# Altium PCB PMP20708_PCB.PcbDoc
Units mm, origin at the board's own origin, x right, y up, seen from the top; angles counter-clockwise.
Board outline 41 x 30 mm, 2 copper layers (Top Layer, Bottom Layer), stack 1.575 mm thick; 39 components, 23 nets, 89 pads, 0 vias.
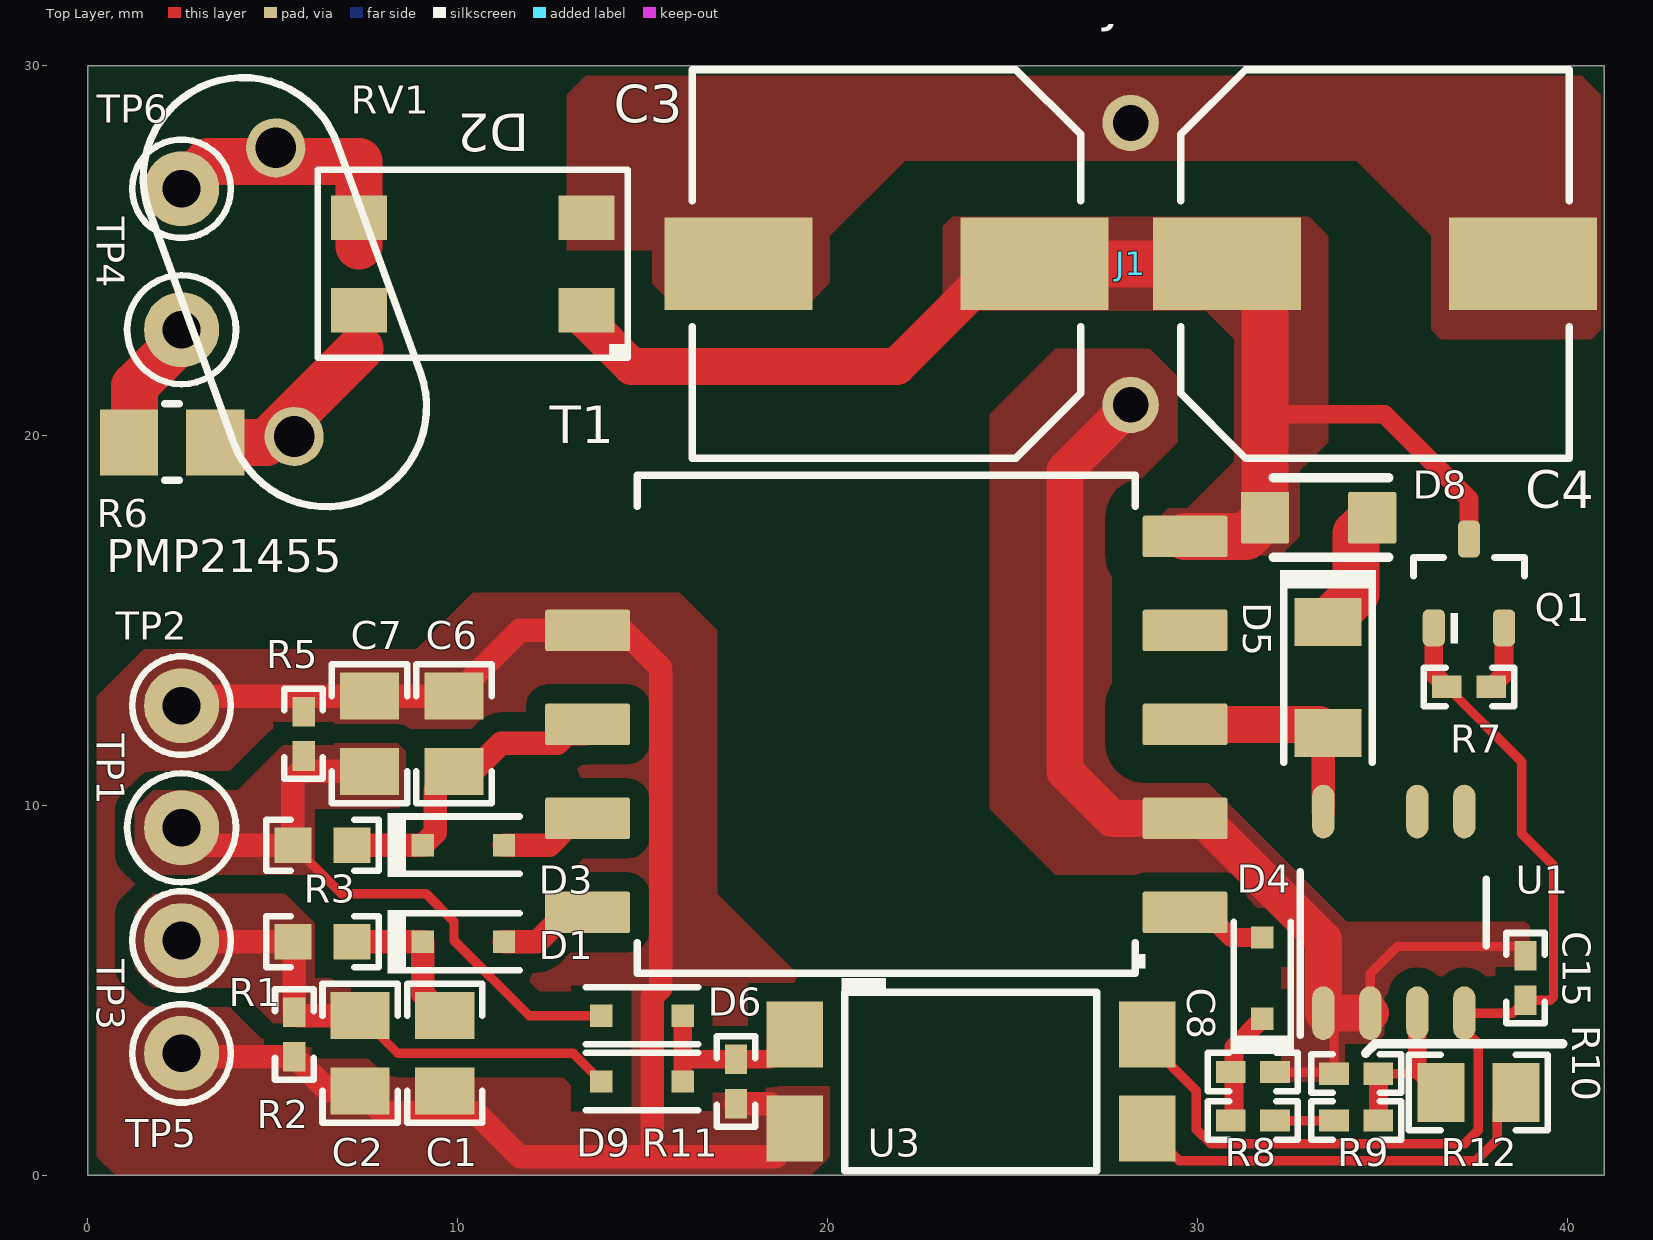
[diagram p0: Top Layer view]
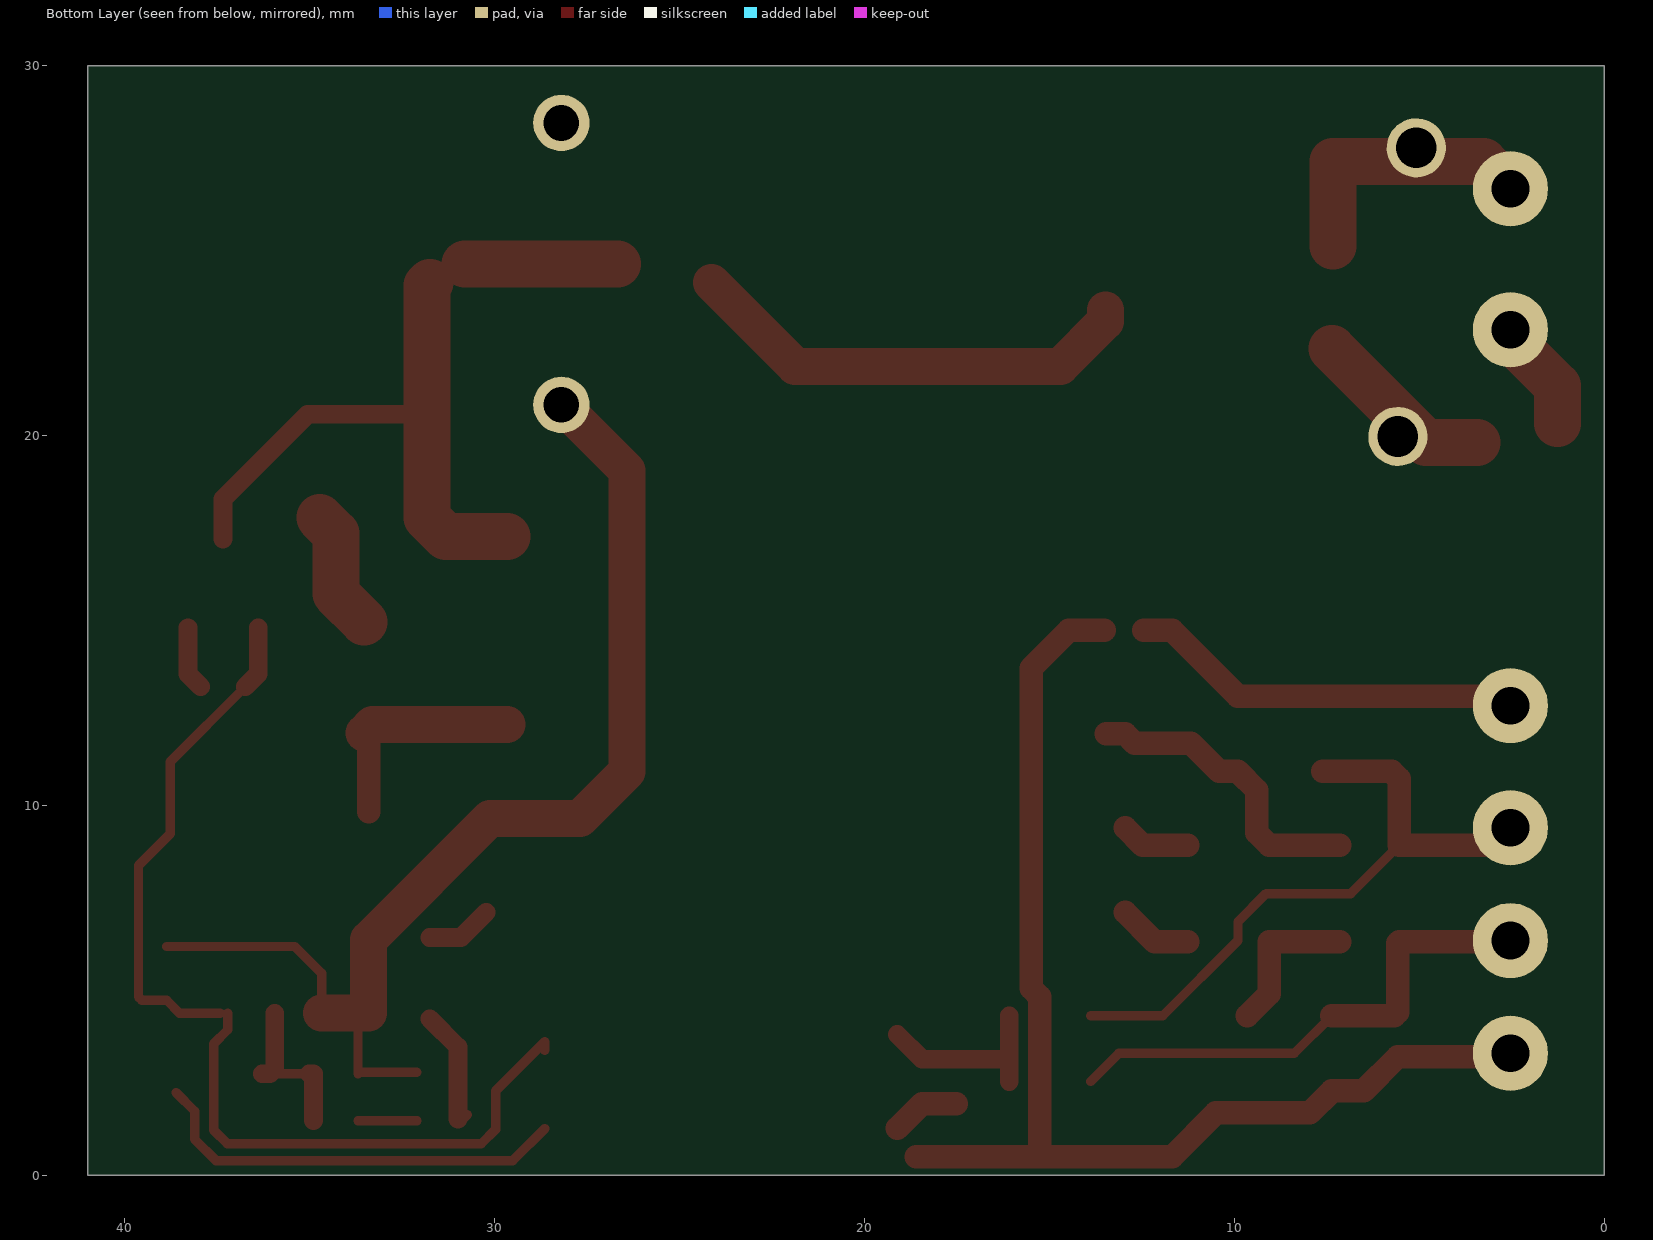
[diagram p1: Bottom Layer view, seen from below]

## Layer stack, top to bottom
Top Solder: solder mask 0.0102, Solder Resist, Dk 3.5
Top Layer: signal copper 0.0356
Dielectric1: core 1.5037, FR-4, Dk 4.8
Bottom Layer: signal copper 0.0356
Bottom Solder: solder mask 0.0102, Solder Resist, Dk 3.5

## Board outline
0,0 41,0 41,30 0,30

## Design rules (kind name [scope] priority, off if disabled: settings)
AcuteAngle [All] p1: minimum=4.50000000000000E+0001 checktracksonly=FALSE
AssemblyTestPointUsage [All] p1: valid=2
Clearance Clearance_2 [InNetClass('HV') vs Not InNetClass('HV')] p1: gap=1.016 ignorepadtopadclearanceinfootprint=FALSE except(0: Arc-Hole Track-Hole SMDPad-Hole THPad-Hole Via-Hole Fill-Hole Poly-Hole Region-Hole Text-Hole)
Clearance Clearance_Keepouts [((IsTrack Or IsArc) And Not InPoly) And IsFree and IsKeepOut vs ((IsTrack Or IsArc) And Not InPoly) And IsFree and IsKeepOut] p2: gap=0 ignorepadtopadclearanceinfootprint=FALSE
Clearance Clearance_BoardEdge_MountingHoles [OnCopper and InComponentClass('Mounting Holes') vs IsKeepOut] p3: gap=1.016 ignorepadtopadclearanceinfootprint=FALSE except(0: Arc-Hole Track-Hole SMDPad-Hole THPad-Hole Via-Hole Fill-Hole Poly-Hole Region-Hole Text-Hole)
Clearance Clearance_BoardEdge_Poly [OnCopper and InPoly vs IsKeepOut] p4: gap=0.635 ignorepadtopadclearanceinfootprint=FALSE except(0: Arc-Hole Track-Hole SMDPad-Hole THPad-Hole Via-Hole Fill-Hole Poly-Hole Region-Hole Text-Hole)
Clearance Clearance_BoardEdge [OnCopper and Not InComponentClass('Logo') and not InComponentClass('FiducialMark') and not InRegion(1000,500,4000,800) and Not IsKeepout vs IsKeepOut] p5: gap=1.905 ignorepadtopadclearanceinfootprint=FALSE except(0: Arc-Hole Track-Hole SMDPad-Hole THPad-Hole Via-Hole Fill-Hole Poly-Hole Region-Hole Text-Hole)
Clearance Clearance_Poly [InPolygon] p6: gap=0.508 ignorepadtopadclearanceinfootprint=FALSE except(0: Arc-Hole Track-Hole SMDPad-Hole THPad-Hole Via-Hole Fill-Hole Poly-Hole Region-Hole Text-Hole)
Clearance [All] p7: gap=0.2 ignorepadtopadclearanceinfootprint=FALSE except(0: Arc-Hole Track-Hole SMDPad-Hole THPad-Hole Via-Hole Fill-Hole Poly-Hole Region-Hole Text-Hole)
ComponentClearance ComponentClearance_MountingHoles_FiducialMarks [InComponentClass('Mounting Holes') vs InComponentClass('FiducialMark')] p1: gap=0.508 collisioncheckmode=3 verticalgap=0.254 showdistances=FALSE
ComponentClearance ComponentClearance_Shunt [InComponentClass('Header') vs InComponentClass('Shunt')] p2: gap=0 collisioncheckmode=3 verticalgap=0 showdistances=FALSE
ComponentClearance ComponentClearance_Logo [InComponentClass('Logo')] p3: gap=0.127 collisioncheckmode=3 verticalgap=0.254 showdistances=FALSE
ComponentClearance ComponentClearance_ScrewToNut [(HasFootprint('NY PMS 440 0025 PH')) vs (HasFootprint('Keystone_1902C'))] p4: gap=0.508 collisioncheckmode=3 verticalgap=2540 showdistances=FALSE
ComponentClearance ComponentClearance_MountingHoles [InComponentClass('Mounting Holes')] p5: gap=0.508 collisioncheckmode=3 verticalgap=0.254 showdistances=FALSE
ComponentClearance ComponentClearance_SmallPassives [HasFootprint('0201*') or HasFootprint('0402*') or HasFootprint('0508') or HasFootprint('0603*') or HasFootprint('0612') or HasFootprint('0805*') or HasFootprint('0815*') or HasFootprint('0830*') or HasFootprint('1206*') or HasFootprint('1210*') or HasFootprint('1808*') or HasFootprint('1812*') or HasFootprint('1825*') or HasFootprint('2010*') or HasFootprint('2220*') or HasFootprint('2225*') or HasFootprint('2512*') or HasFootprint('2728*') or HasFootprint('3518*') vs HasFootprint('0201*') or HasFootprint('0402*') or HasFootprint('0508') or HasFootprint('0603*') or HasFootprint('0612') or HasFootprint('0805*') or HasFootprint('0815*') or HasFootprint('0830*') or HasFootprint('1206*') or HasFootprint('1210*') or HasFootprint('1808*') or HasFootprint('1812*') or HasFootprint('1825*') or HasFootprint('2010*') or HasFootprint('2220*') or HasFootprint('2225*') or HasFootprint('2512*') or HasFootprint('2728*') or HasFootprint('3518*')] p6: gap=0.508 collisioncheckmode=3 verticalgap=0.508 showdistances=FALSE
ComponentClearance ComponentClearance_THtoSMT [IsThruComponent vs IsSMTComponent] p7: gap=0.254 collisioncheckmode=3 verticalgap=0.254 showdistances=FALSE
ComponentClearance ComponentClearance_THtoTH [IsThruComponent vs IsThruComponent] p8: gap=0.254 collisioncheckmode=3 verticalgap=0.254 showdistances=FALSE
ComponentClearance [All] p9: gap=0.254 collisioncheckmode=3 verticalgap=0.254 showdistances=FALSE
DiffPairsRouting [All] p1: maxlimit=2.54 minlimit=0.254 mostfreqgap=0.254 toplayer_minwidth=0.381 toplayer_maxwidth=0.381 toplayer_prefwidth=0.381 bottomlayer_minwidth=0.381 bottomlayer_maxwidth=0.381 bottomlayer_prefwidth=0.381 maxuncoupledlength=25.4
FabricationTestPointUsage TestPointUsage [All] p1: valid=2 allowmultiple=FALSE
FabricationTestpoint Testpoint [All] p1: side=3 testpointundercomponent=TRUE minsize=1.016 maxsize=2.54 preferedsize=1.524 minholesize=0 maxholesize=1.016 preferedholesize=0.813 testpointgrid=0.025 allowsidetop=TRUE allowsidebottom=TRUE usegrid=TRUE gridtolerance=0
FanoutControl Fanout_LCC [IsLCC] p1: bgadir=Out bgaviamode=Centered fanoutstyle=Auto fanoutdirection=Alternating viagrid=0.025 // Fanout_LCC (Default Rule)
FanoutControl Fanout_BGA [IsBGA] p2: bgadir=Out bgaviamode=Centered fanoutstyle=Auto fanoutdirection=Alternating viagrid=0.025 // Fanout_BGA (Default Rule)
FanoutControl Fanout_Default [All] p4: bgadir=Out bgaviamode=Centered fanoutstyle=Auto fanoutdirection=Alternating viagrid=0.025 // Fanout_Default (Default Rule)
FanoutControl Fanout_Small [(CompPinCount < 5)] p5: bgadir=Out bgaviamode=Centered fanoutstyle=Auto fanoutdirection=OutThenIn viagrid=0.025 // Fanout_Small (Default Rule)
Height [All] p1: minheight=0 maxheight=76.2 prefheight=12.7
HoleSize [All] p1: absolutevalues=TRUE maxlimit=6.375 minlimit=0.178 maxpercent=80.000 minpercent=20.000
MinimumAnnularRing MinimumAnnularRing_ThermalPadVias [IsVia and InAnyComponent] p1: minimumring=0.15
MinimumAnnularRing [All] p2: minimumring=0.124
MinimumSolderMaskSliver MinimumSolderMaskSliver_Logo [InComponentClass('Logo') vs InComponentClass('Logo')] p1: minsoldermaskwidth=0.018
MinimumSolderMaskSliver [All] p2: minsoldermaskwidth=0.051
PlaneConnect [All] p1: planeconnectstyle=Relief reliefexpansion=0.254 reliefentries=4 reliefconductorwidth=0.254 reliefairgap=0.254
PolygonConnect PolygonConnect_12 [All vs IsNamedPolygon('VREC') Or  IsNamedPolygon('24V') Or  IsNamedPolygon('C3_2') Or  IsNamedPolygon('GND') Or  IsNamedPolygon('RTN') Or  IsNamedPolygon('5V')] p1: connectstyle=Direct reliefconductorwidth=0.254 reliefentries=4 polygonreliefangle="90 Angle" airgapwidth=0.254
PolygonConnect PolygonConnect_11 [All vs IsNamedPolygon('VREC') Or  IsNamedPolygon('RTN') Or  IsNamedPolygon('C3_2')] p2: connectstyle=Direct reliefconductorwidth=0.254 reliefentries=4 polygonreliefangle="90 Angle" airgapwidth=0.254
PolygonConnect PolygonConnect_10 [All vs IsNamedPolygon('RTN') Or  IsNamedPolygon('C3_2') Or  IsNamedPolygon('VREC')] p3: connectstyle=Direct reliefconductorwidth=0.254 reliefentries=4 polygonreliefangle="90 Angle" airgapwidth=0.254
PolygonConnect PolygonConnect_9 [All vs IsNamedPolygon('C11_1') Or  IsNamedPolygon('Vin') Or  IsNamedPolygon('Vin') Or  IsNamedPolygon('5V') Or  IsNamedPolygon('D6_2') Or  IsNamedPolygon('Q3_3') Or  IsNamedPolygon('GND2') Or  IsNamedPolygon('GND2') Or  IsNamedPolygon('GND') Or  IsNamedPolygon('Q3_4') Or  IsNamedPolygon('12V5') Or  IsNamedPolygon('GND') Or  IsNamedPolygon('12V5') Or  IsNamedPolygon('D3_1')] p4: connectstyle=Direct reliefconductorwidth=0.254 reliefentries=4 polygonreliefangle="90 Angle" airgapwidth=0.254
PolygonConnect PolygonConnect_8 [All vs IsNamedPolygon('C11_1') Or  IsNamedPolygon('Vin') Or  IsNamedPolygon('12V5') Or  IsNamedPolygon('Q3_3') Or  IsNamedPolygon('GND2') Or  IsNamedPolygon('GND2') Or  IsNamedPolygon('5V') Or  IsNamedPolygon('Q3_4') Or  IsNamedPolygon('12V5')] p5: connectstyle=Direct reliefconductorwidth=0.254 reliefentries=4 polygonreliefangle="90 Angle" airgapwidth=0.254
PolygonConnect PolygonConnect_7 [All vs IsNamedPolygon('GND2') Or  IsNamedPolygon('GND2') Or  IsNamedPolygon('5V') Or  IsNamedPolygon('12V5') Or  IsNamedPolygon('12V5') Or  IsNamedPolygon('C11_1')] p6: connectstyle=Direct reliefconductorwidth=0.254 reliefentries=4 polygonreliefangle="90 Angle" airgapwidth=0.254
PolygonConnect PolygonConnect_6 [All vs IsNamedPolygon('GND2') Or  IsNamedPolygon('SGND') Or  IsNamedPolygon('GND1') Or  IsNamedPolygon('C901_1') Or  IsNamedPolygon('SGND') Or  IsNamedPolygon('GND2') Or  IsNamedPolygon('GND1')] p7: connectstyle=Direct reliefconductorwidth=0.254 reliefentries=4 polygonreliefangle="90 Angle" airgapwidth=0.254
PolygonConnect PolygonConnect_5 [All vs IsNamedPolygon('GND1') Or  IsNamedPolygon('GND1')] p8: connectstyle=Direct reliefconductorwidth=0.254 reliefentries=4 polygonreliefangle="90 Angle" airgapwidth=0.254
PolygonConnect PolygonConnect_4 [All vs IsNamedPolygon('C21_1') Or  IsNamedPolygon('C5_1') Or  IsNamedPolygon('C12_2') Or  IsNamedPolygon('C2_2') Or  IsNamedPolygon('C13_1') Or  IsNamedPolygon('C28_1') Or  IsNamedPolygon('C6_1') Or  IsNamedPolygon('GND') Or  IsNamedPolygon('GND2') Or  IsNamedPolygon('C14_1') Or  IsNamedPolygon('C13_1') Or  IsNamedPolygon('Q1_3') Or  IsNamedPolygon('C14_1') Or  IsNamedPolygon('C5_1') Or  IsNamedPolygon('GND2') Or  IsNamedPolygon('C28_1') Or  IsNamedPolygon('D5_2') Or  IsNamedPolygon('D6_2') Or  IsNamedPolygon('D2_1') Or  IsNamedPolygon('C12_2') Or  IsNamedPolygon('D2_1') Or  IsNamedPolygon('C4_1') Or  IsNamedPolygon('C4_1') Or  IsNamedPolygon('C2_2') Or  IsNamedPolygon('GND') Or  IsNamedPolygon('C33_1') Or  IsNamedPolygon('C9_1')] p9: connectstyle=Direct reliefconductorwidth=0.254 reliefentries=4 polygonreliefangle="90 Angle" airgapwidth=0.254
PolygonConnect PolygonConnect_3 [All vs IsNamedPolygon('C28_1') Or  IsNamedPolygon('C12_2') Or  IsNamedPolygon('C28_1') Or  IsNamedPolygon('C9_1') Or  IsNamedPolygon('D5_2') Or  IsNamedPolygon('C12_2') Or  IsNamedPolygon('C2_2') Or  IsNamedPolygon('C14_1') Or  IsNamedPolygon('C4_1') Or  IsNamedPolygon('C14_1') Or  IsNamedPolygon('D6_2') Or  IsNamedPolygon('GND2') Or  IsNamedPolygon('Q1_3') Or  IsNamedPolygon('C5_1') Or  IsNamedPolygon('D2_1') Or  IsNamedPolygon('C4_1') Or  IsNamedPolygon('C13_1') Or  IsNamedPolygon('C5_1') Or  IsNamedPolygon('C13_1') Or  IsNamedPolygon('C33_1') Or  IsNamedPolygon('D2_1') Or  IsNamedPolygon('GND') Or  IsNamedPolygon('GND') Or  IsNamedPolygon('GND2') Or  IsNamedPolygon('C2_2') Or  IsNamedPolygon('C6_1') Or  IsNamedPolygon('C21_1')] p10: connectstyle=Direct reliefconductorwidth=0.254 reliefentries=4 polygonreliefangle="90 Angle" airgapwidth=0.254
PolygonConnect PolygonConnect_2 [All vs IsNamedPolygon('C21_1') Or  IsNamedPolygon('C4_1') Or  IsNamedPolygon('D5_2') Or  IsNamedPolygon('C5_1') Or  IsNamedPolygon('C14_1') Or  IsNamedPolygon('C13_1') Or  IsNamedPolygon('C4_1') Or  IsNamedPolygon('C33_1') Or  IsNamedPolygon('C12_2') Or  IsNamedPolygon('D2_1') Or  IsNamedPolygon('C2_2') Or  IsNamedPolygon('C28_1') Or  IsNamedPolygon('C12_2') Or  IsNamedPolygon('D2_1') Or  IsNamedPolygon('C5_1') Or  IsNamedPolygon('Q1_3') Or  IsNamedPolygon('GND') Or  IsNamedPolygon('D6_2') Or  IsNamedPolygon('C6_1') Or  IsNamedPolygon('C2_2') Or  IsNamedPolygon('C14_1') Or  IsNamedPolygon('C28_1') Or  IsNamedPolygon('C13_1') Or  IsNamedPolygon('C9_1') Or  IsNamedPolygon('GND')] p11: connectstyle=Direct reliefconductorwidth=0.254 reliefentries=4 polygonreliefangle="90 Angle" airgapwidth=0.254
PolygonConnect PolygonConnect_1 [All vs IsNamedPolygon('C28_1') Or  IsNamedPolygon('D5_2') Or  IsNamedPolygon('C5_1') Or  IsNamedPolygon('C5_1') Or  IsNamedPolygon('D2_1') Or  IsNamedPolygon('C21_1') Or  IsNamedPolygon('C9_1') Or  IsNamedPolygon('C4_1') Or  IsNamedPolygon('C14_1') Or  IsNamedPolygon('C28_1') Or  IsNamedPolygon('C6_1') Or  IsNamedPolygon('C12_2') Or  IsNamedPolygon('C33_1') Or  IsNamedPolygon('C4_1') Or  IsNamedPolygon('C13_1') Or  IsNamedPolygon('C12_2') Or  IsNamedPolygon('D6_2') Or  IsNamedPolygon('C2_2') Or  IsNamedPolygon('C14_1') Or  IsNamedPolygon('D2_1') Or  IsNamedPolygon('C2_2') Or  IsNamedPolygon('C13_1')] p12: connectstyle=Direct reliefconductorwidth=0.254 reliefentries=4 polygonreliefangle="90 Angle" airgapwidth=0.254
PolygonConnect [All] p13: connectstyle=Relief reliefconductorwidth=0.254 reliefentries=4 polygonreliefangle="90 Angle" airgapwidth=0.254
RoutingVias ThermalPadVias [IsVia and InAnyComponent] p1: holewidth=0.2 width=0.5 viastyle="Through Hole" minholewidth=0.2 minwidth=0.5 maxholewidth=0.33 maxwidth=0.6
RoutingVias [All] p2: holewidth=0.406 width=0.864 viastyle="Through Hole" minholewidth=0.2 minwidth=0.508 maxholewidth=1.016 maxwidth=1.651
SilkToBoardRegionClearance [Not ((IsComment or IsDesignator) And (Hide <> 'False')) and not InRegion(1000,500,4000,800)] p1:
SilkToSilkClearance SilkToSilkClearance_Pb-FreeLogo [(HasFootprint('Pb-Free_Overlay_Medium') OR HasFootprint('Pb-Free_Overlay_Small')) vs (HasFootprint('Pb-Free_Overlay_Medium') OR HasFootprint('Pb-Free_Overlay_Small'))] p1: silktosilkclearance=0
SilkToSilkClearance [All] p2: silktosilkclearance=0.025
SilkToSolderMaskClearance "Silk to Solder Mask Opening" [All] p1: minsilkscreentomaskgap=0.025 clearancetoexposedcopper=FALSE
SolderMaskExpansion [All] p1: expansion=0.05
Width [All] p1: maxlimit=2.54 minlimit=0.152 preferedwidth=0.254 checkconnectedcopper=TRUE
14 further rules are at their usual default settings.

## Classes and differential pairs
net class HV: NetD2_3 NetD2_4 NetD5_1 NetD5_2 NetR6_1 VREC

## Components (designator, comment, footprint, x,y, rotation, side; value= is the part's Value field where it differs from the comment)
C1 "C2012X5R1V106K085AC" 0805_HV 9.652,3.302 r270 top
C2 "C2012X5R1V106K085AC" 0805_HV 7.366,3.302 r270 top
C3 "ULR2G8R2MNL1GS" ULV_1000x1350 21.59,24.638 r180 top
C4 "ULR2G8R2MNL1GS" ULV_1000x1350 34.798,24.638 r0 top
C6 "C2012X7R1A106K125AC" 0805_HV 9.906,11.938 r270 top
C7 "C2012X7R1A106K125AC" 0805_HV 7.62,11.938 r270 top
C8 "160R07X104KV4T" 0402_065 31.496,2.794 r180 top
C15 "C1005X6S1C105K050BC" 0402 38.862,5.334 r270 top
D1 "BAS21HT1G" SOD-323 10.16,6.316 r0 top
D2 "RH06-T" MiniDIP 10.414,24.638 r180 top
D3 "BAS21HT1G" SOD-323 10.16,8.927 r0 top
D4 "BAS21HT1G" SOD-323 31.75,5.334 r90 top
D5 "CSFMT108-HF" SOD-123H 33.528,13.462 r270 top
D6 "VDZT2R4.7B" SOD-323-Bi 14.986,4.318 r0 top
D8 "BZD27C200P-E3-08" DO-219AB 33.274,17.78 r180 top
D9 "TFZVTR24B" SOD-323-Bi 14.986,2.54 r0 top
J1 "923345-03-C" 923345-03-C 28.194,24.638 r270 top
Q1 "BSS126 H6906" SOT-23 37.338,16.002 r90 top
R1 "CRCW06031R00FKEA" 0603 6.35,6.316 r180 top
R2 "CRCW040220K0FKED" 0402 5.588,3.81 r90 top
R3 "CRCW06031R00FKEA" 0603 6.35,8.927 r180 top
R5 "CRCW04025K10JNED" 0402 5.842,11.938 r270 top
R6 "FCR1206J10R" WSLP1206-001 2.286,19.812 r0 top
R7 "CRCW04029K09FKED" 0402 37.338,13.208 r0 top
R8 "CRCW04020000Z0ED" 0402 31.496,1.482 r0 top
R9 "CRCW04023K74FKED" 0402 34.29,1.482 r180 top
R10 "CRCW0402511RFKED" 0402 34.29,2.752 r0 top
R11 "CRCW040210K0FKED" 0402 17.526,2.54 r90 top
R12 "CRCW08050000Z0EA" 0805_HV 37.592,2.244 r0 top
RV1 "B72207S301K111" VAR_S10K275E2 5.334,23.876 r290 top
T1 "750316908" Wurth_750316908 21.59,12.192 r180 top
TP1 "5000" Keystone5000 2.54,9.398 r0 top
TP2 "5001" Keystone5001 2.54,12.7 r0 top
TP3 "5000" Keystone5000 2.54,6.35 r90 top
TP4 "5000" Keystone5000 2.54,22.86 r270 top
TP5 "5001" Keystone5001 2.54,3.302 r0 top
TP6 "5001" Keystone5001 2.54,26.67 r270 top
U1 "UCC28881DR" D0007A_N 35.306,7.112 r90 top
U3 "SFH6186-4T" SMD-4 23.876,2.54 r0 top

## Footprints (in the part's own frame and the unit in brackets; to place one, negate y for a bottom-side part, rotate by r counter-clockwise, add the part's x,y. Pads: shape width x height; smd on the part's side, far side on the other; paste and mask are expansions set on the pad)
0402 [mm] "0402 from SM-752 data"
  rect 0.8x0.6 smd: 1(-0.6,0) 2(0.6,0)
  silkscreen extent -1.22,-0.52 1.22,0.52, body extent -0.55,-0.3 0.55,0.3, height 0.6
0402_065 [mm] "0402"
  rect 0.8x0.6 smd: 1(-0.6,0) 2(0.6,0)
  silkscreen extent -1.22,-0.52 1.22,0.52, body extent -0.55,-0.3 0.55,0.3, height 0.65
0603 [mm] "0603 from SM-752 data"
  rect 1x0.95 smd: 1(-0.8,0) 2(0.8,0)
  silkscreen extent -1.52,-0.69 1.52,0.69, body extent -0.87,-0.47 0.87,0.47, height 1
0805_HV [mil] "0805 with 30mil clearance between pads"
  rect 50x63 smd: 1(-40,0) 2(40,0)
  silkscreen extent -74,-40 74,40, body extent -43,-29 43,29, height 57
923345-03-C [mil] "Wire Jumper"
  round 60 hole 38: 1(-150,0) 2(150,0)
  body extent -163,-40 163,37, height 100
D0007A_N [mm] "SOIC, 7-Leads, Body 4.9x3.9mm, Pitch 1.27mm, IPC Medium Density"
  oval 1.45x0.6 smd: 1(-2.725,1.905) 2(-2.725,0.635) 3(-2.725,-0.635) 4(-2.725,-1.905) 5(2.725,-1.905) 6(2.725,-0.635) 8(2.725,1.905)
  silkscreen extent -3.32,-2.5 1.1,2.52, body extent -3.01,-2.45 3.01,2.45, height 1.75
DO-219AB [mm] "Vishay Semiconductor"
  rrect8% 1.3x1.4 smd: 1(-1.45,0) 2(1.45,0)
  silkscreen extent -1.9,-1.07 1.23,1.07, body extent -1.95,-0.95 1.95,0.95, height 1.09
Keystone5000 [mil] "For Keystone 500x miniature loop terminals"
  round 80 hole 40: 1(0,0)
  silkscreen extent -58,-58 58,58, body extent -49,-49 49,49, height 182
Keystone5001 [mil] "For Keystone 500x miniature loop terminals"
  round 80 hole 40: 1(0,0)
  silkscreen extent -52,-52 52,52, body extent -49,-49 49,49, height 182
MiniDIP [mm] "Land pattern created based on STEP model."
  rect 1.52x1.2 smd: 1(-3.075,1.25) 2(-3.075,-1.25) 3(3.075,-1.25) 4(3.075,1.25)
  silkscreen extent -4.19,-2.54 4.19,2.54, body extent -3.5,-2.45 3.5,2.45, height 2.75
SMD-4 [mm] "SMD, 4-Leads, Body 4.83x6.81mm, Pitch 2.54mm"
  rect 1.525x1.78 smd: 1(-4.763,1.27) 2(-4.763,-1.27) 3(4.763,-1.27) 4(4.763,1.27)
  silkscreen extent -3.5,-2.42 3.41,2.8, body extent -5.02,-2.42 5.02,2.42, height 3.91
SOD-123H [mm] "SMT, 2-Leads, Body 3.5x1.6mm"
  rect 1.3x1.8 smd: 1(-1.5,0) 2(1.5,0)
  silkscreen extent -2.9,-1.3 2.3,1.3, body extent -1.9,-0.9 1.9,0.9, height 1
SOD-323 [mm] "NXP recommended land pattern"
  rect 0.6x0.6 smd paste-0.05: 1(-1.1,0) 2(1.1,0)
  silkscreen extent -2.06,-0.86 1.53,0.86, body extent -1.3,-0.67 1.3,0.68, height 1.1
SOD-323-Bi [mm] "SOD323, 2-Leads, Body 1.9x1.45mm, No Polarity Mark"
  rect 0.6x0.6 smd paste-0.05: 1(-1.1,0) 2(1.1,0)
  silkscreen extent -1.53,-0.77 1.53,0.77, body extent -1.27,-0.65 1.27,0.65, height 1.02
SOT-23 [mm] "SOT23, 3-Leads, Body 2.9x1.3mm, Pitch 0.95mm, Lead Span 2.5mm, IPC Medium Density"
  rrect50% 1x0.6 smd: 1(-1.2,0.95) 2(-1.2,-0.95) 3(1.2,0)
  silkscreen extent -1.63,-1.5 0.7,1.5, body extent -1.16,-1.45 1.21,1.45, height 1
ULV_1000x1350 [mm] "SMD, 2-Leads, Dia 10mm"
  rect 4x2.5 smd: 1(-4,0) 2(4,0)
  silkscreen extent -5.25,-5.25 5.25,5.25, body extent -5.25,-5.25 5.25,5.25, height 14.51
VAR_S10K275E2 [mm] "EPCOS"
  round 1.6 hole 1.1: 1(-3.75,1.1) 2(3.75,-1.1)
  silkscreen extent -6,-2.7 6,2.7, body extent -5.98,-2.7 5.98,2.7, height 14.99
WSLP1206-001 [mm] "Vishay"
  rect 1.57x1.78 smd: 1(-1.165,0) 2(1.165,0)
  silkscreen extent -0.2,-1.02 0.2,1.05, body extent -1.73,-0.93 1.73,0.93, height 0.89
Wurth_750316908 [mm] "SMD, 10-Leads, Body 17.66x13.72mm, Pitch 2.54mm"
  rrect9% 2.29x1.12 smd: 1(-8.075,5.08) 2(-8.075,2.54) 3(-8.075,0) 4(-8.075,-2.54) 5(-8.075,-5.08) 7(8.075,-2.54) 8(8.075,0) 9(8.075,2.54) 10(8.075,5.08)
  silkscreen extent -7,-6.73 6.73,6.73, body extent -8.83,-6.86 8.83,6.86, height 10.5

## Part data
C1 C2: "CAP, CERM, 10 µF, 35 V, +/- 10%, X5R, 0805"
C3 C4: library part ULV2G100MNL1GS, "CAP ALUM 8.2UF 20% 400V SMD"
C6 C7: "CAP, CERM, 10 µF, 10 V, +/- 10%, X7R, 0805"
C8: "CAP, CERM, 0.1 µF, 16 V, +/- 10%, X5R, 0402"
C15: "CAP, CERM, 1 µF, 16 V, +/- 10%, X6S, 0402"
D1 D3 D4: library part BAS20HT1G, "DIODE GEN PURP 250V 200MA SOD323"
D2: "Diode, Switching-Bridge, 600V, 0.5A, MiniDIP"
D5: "Diode, Superfast Rectifier, 600 V, 1 A, 3.5x1.6mm"
D6: library part PESD24VL1BA,115, "DIODE ZENER 4.7V 100MW VMD2"
D8: "Diode, Zener, 200 V, 800 mW, AEC-Q101, DO-219AB"
D9: library part PESD24VL1BA,115, "Zener Diode 500mW ±3% Surface Mount SOD-323HE"
J1: "Jumper Wire, 300mil spacing, Orange, pkg of 200"
Q1: "MOSFET, N-CH, 600 V, 0.021 A, AEC-Q101, SOT-23"
R1 R3: "RES, 1.00, 1%, 0.1 W, 0603"
R2: "RES, 20.0 k, 1%, 0.063 W, 0402"
R5: "RES, 5.1 k, 5%, 0.063 W, 0402"
R6: library part WSLP12061L000FEA, "RES SMD 10 OHM 5% 1/8W 1206"
R7: "RES, 9.09 k, 1%, 0.063 W, 0402"
R8: "RES, 0, 5%, 0.063 W, 0402"
R9: "RES, 3.74 k, 1%, 0.063 W, 0402"
R10: "RES, 511, 1%, 0.063 W, 0402"
R11: "RES, 10.0 k, 1%, 0.063 W, 0402"
R12: "RES, 0, 5%, 0.125 W, 0805"
RV1: library part S10K275E2, "VARISTOR 470V 1.2KA DISC 7MM"
T1: "Transformer, 450 uH, SMT"
TP1 TP3 TP4: "Test Point, Miniature, Red, TH"
TP2 TP5 TP6: "Test Point, Miniature, Black, TH"
U1: library part UCC28880DR, "700-V Lowest Quiescent Current Off-Line Switcher, D0007A"
U3: library part SFH6156-2T, "OPTOISOLATOR 5.3KV TRANS 4SMD"

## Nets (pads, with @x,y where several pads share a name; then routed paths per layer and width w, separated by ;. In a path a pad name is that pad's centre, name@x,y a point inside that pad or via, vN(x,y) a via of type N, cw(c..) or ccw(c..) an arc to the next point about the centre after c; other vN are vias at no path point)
5V: C7.2 D6.1 R3.2 R5.2 TP1.1 | length 17
  Top Layer w0.254: R3.2 6.857,7.62 9.144,7.62 9.906,6.858 9.906,6.35 11.938,4.318 D6.1
  Top Layer w0.635: TP1.1@3.011,8.927 R3.2 5.55,10.719 5.753,10.922 C7.2
24V: C2.1 D9.1 R1.2 R2.2 TP3.1 | length 13.8
  Top Layer w0.254: C2.1 8.382,3.302 13.124,3.302 D9.1
  Top Layer w0.635: TP3.1@2.574,6.316 R1.2 ; R2.2 R1.2@5.588,6.278 ; R2.2@5.68,4.318 C2.1
GND: C1.2 C2.2 C6.1 C7.1 R2.1 R5.1 R11.1 T1.7 TP2.1 TP5.1 U3.2 | length 45.4
  Top Layer w0.635: TP2.1 2.794,12.954 C7.1 C6.1 11.684,14.732 T1.7@12.446,14.732 ; TP5.1@2.632,3.21 R2.1 6.512,2.286 C2.2 7.963,1.689 10.503,1.689 11.684,0.508 15.24,0.508 ; T1.7 14.478,14.732 15.494,13.716 15.494,5.058 15.269,4.832 15.269,0.537 15.24,0.508 ; R11.1 18.443,1.94 U3.2 ; U3.2@18.605,0.508 15.24,0.508
NetC1_1: C1.1 D1.1 R1.1 | length 4.2
  Top Layer w0.635: R1.1 D1.1 9.06,4.91 C1.1
NetC3_2: C3.2 C4.2 D2.2 J1.1
NetC6_2: C6.2 D3.1 R3.1 T1.8 | length 8.2
  Top Layer w0.635: R3.1 D3.1 9.398,9.265 9.398,10.414 C6.2 10.414,10.922 11.176,11.684 12.7,11.684 12.954,11.938 T1.8@13.462,11.938
NetC15_2: C15.2 Q1.1 R7.1 U1.4 U3.4 | length 28
  Top Layer w0.254: U3.4@28.639,3.381 U3.4@28.639,3.556 ; U3.4@28.639,3.619 29.972,2.286 29.972,1.244 30.361,0.855 37.219,0.855 37.592,1.228 ; R7.1 38.77,11.176 38.77,9.231 39.624,8.377 39.624,4.826 39.532,4.734 C15.2 38.515,4.387 U1.4@37.416,4.387 ; U1.4 37.211,3.937 37.592,3.556 37.592,1.27
  Top Layer w0.508: Q1.1 36.388,13.558 R7.1
NetD1_2: D1.2 T1.10 | length 2
  Top Layer w0.635: D1.2 12.158,6.316 T1.10@12.954,7.112
NetD2_3: D2.3 RV1.1 TP6.1 | length 7
  Top Layer w1.27: TP6.1@2.794,26.924 3.275,27.405 7.339,27.405 7.339,25.126
NetD2_4: D2.4 R6.2 RV1.2 | length 5
  Top Layer w1.27: R6.2 4.826,19.812 7.366,22.352
NetD3_2: D3.2 T1.9 | length 1.9
  Top Layer w0.635: D3.2 12.483,8.927 T1.9@12.954,9.398
NetD4_2: D4.2 T1.1 | length 1.8
  Top Layer w0.508: T1.1@30.226,7.112 30.904,6.434 D4.2
NetD5_1: D5.1 D8.1 | length 3.3
  Top Layer w1.27: D5.1 34.29,15.724 34.29,17.346 D8.1
NetD5_2: D5.2 T1.3 U1.8 | length 6.1
  Top Layer w0.635: U1.8 33.401,11.835 D5.2
  Top Layer w1: T1.3 33.298,12.192 D5.2
NetD6_2: D6.2 D9.2 R11.2 U3.1 | length 5.1
  Top Layer w0.508: D9.2 16.086,3.19 ; D6.2 16.086,3.19 ; U3.1 18.444,3.14 R11.2 16.136,3.14 16.086,3.19
NetQ1_2: Q1.2 R7.2 | length 1.7
  Top Layer w0.508: R7.2 38.288,13.558 Q1.2
NetR6_1: R6.1 TP4.1 | length 3.2
  Top Layer w1.27: R6.1@1.27,20.32 1.27,21.336 TP4.1@2.794,22.86
NetR8_2: R8.2 R9.2 | length 1.6
  Top Layer w0.254: R8.2 R9.2
NetR9_1: R9.1 R10.2 R12.1 U1.3 | length 4.6
  Top Layer w0.254: R10.2@34.89,2.632 R10.2@35.01,2.752 ; R10.2@35.052,2.794 R10.2@35.01,2.752 ; U1.3@35.906,4.352 U1.3 ; 35.941,2.921 35.941,2.879 36.068,2.752 R10.2@35.01,2.752
  Top Layer w0.508: R9.1 34.89,2.632 R10.2@34.89,2.702 ; R10.2 R10.2@35.01,2.752 ; 35.941,2.921 U1.3 ; R12.1@36.068,2.752 R12.1@36.28,2.752
NetR12_2: R12.2 U3.3 | length 11.5
  Top Layer w0.254: U3.3 29.507,0.401 37.527,0.401 38.1,0.974 38.1,1.736 R12.2
RTN: C8.1 C15.1 J1.2 R10.1 T1.2 U1.1 U1.2 | length 31.6
  Top Layer w0.254: C8.1@32.103,2.787 R10.1@33.655,2.787 ; U1.1 33.69,4.098 R10.1 ; U1.2 34.671,5.461 35.398,6.188 C15.1@38.862,6.188
  Top Layer w1: J1.2 26.416,19.05 26.416,10.922 27.686,9.652 T1.2 30.122,9.652 33.401,6.373 U1.1 U1.2
VAUX: C8.2 D4.1 R8.1 | length 3.3
  Top Layer w0.254: R8.1@30.734,1.644 R8.1 R8.1@30.896,1.524
  Top Layer w0.508: R8.1@30.988,1.524 30.988,3.472 D4.1
VREC: C3.1 C4.1 D2.1 D8.2 Q1.3 T1.5 | length 32.4
  Top Layer w0.508: 32.258,20.574 35.052,20.574 37.338,18.288 Q1.3
  Top Layer w1: D2.1 13.489,23.087 14.704,21.872 21.872,21.872 C3.1@24.13,24.13
  Top Layer w1.27: C3.1@26.67,24.638 C4.1 ; T1.5 31.316,17.272 D8.2 31.824,24.056 C4.1@31.75,24.13
pads on no net: T1.4 U1.5 U1.6

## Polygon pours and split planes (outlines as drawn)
VREC on Top Layer "VREC" (solid, remove dead copper, pour order 0): 28.956,16.764 32.258,16.764 32.512,17.018 32.766,17.272 32.766,17.526 32.766,19.05 33.274,19.558 33.528,19.812 33.528,20.066 33.528,25.4 33.02,25.908 24.13,25.908 23.368,25.908 23.114,25.654 23.114,24.892 23.114,23.622 23.368,23.368 24.638,23.368 30.226,23.368 30.988,22.606 30.988,21.082 30.988,19.304 29.718,18.034 29.21,18.034 28.956,17.78
RTN on Top Layer "RTN" (solid, remove dead copper, pour order 4): 32.004,2.54 32.766,2.54 34.036,2.54 34.036,3.048 34.29,3.302 34.544,3.556 34.798,3.556 35.052,3.81 35.052,4.572 35.052,4.826 35.56,5.334 36.068,5.334 38.862,5.334 39.116,5.588 39.116,6.096 39.116,6.604 38.862,6.858 38.354,6.858 34.036,6.858 33.02,7.874 30.226,10.668 28.448,10.668 27.686,11.43 27.686,14.986 27.686,18.034 28.702,19.05 29.464,19.812 29.464,20.574 29.464,21.59 29.21,21.844 28.702,22.352 27.432,22.352 26.416,22.352 26.162,22.352 25.146,21.336 24.384,20.574 24.384,13.208 24.384,9.906 26.162,8.128 30.48,8.128 30.734,8.128 32.258,6.604 32.258,5.842 32.258,3.048 32.004,2.794
NetC3_2 on Top Layer "C3_2" (solid, remove dead copper, pour order 2): 12.954,24.638 12.954,26.162 12.954,29.21 13.462,29.718 14.224,29.718 40.386,29.718 40.894,29.21 40.894,28.194 40.894,22.86 40.64,22.606 40.132,22.606 36.576,22.606 36.322,22.86 36.322,23.368 36.322,25.4 34.29,27.432 33.274,27.432 22.098,27.432 20.066,25.4 20.066,24.384 20.066,24.13 19.558,23.622 17.272,23.622 15.748,23.622 14.732,24.638
5V on Top Layer "5V" (solid, remove dead copper, pour order 6): 1.27,9.906 1.778,10.414 2.286,10.414 3.556,10.414 4.064,10.414 5.334,11.684 6.604,11.684 8.382,11.684 8.636,11.43 8.636,11.176 8.636,10.16 8.382,9.906 6.604,9.906 6.35,9.652 6.35,9.144 6.35,8.382 6.096,8.128 5.588,8.128 1.778,8.128 1.27,8.636
24V on Top Layer "24V" (solid, remove dead copper, pour order 8): 1.778,7.62 1.27,7.112 1.27,6.604 1.27,5.588 1.778,5.08 2.032,5.08 4.064,5.08 5.08,4.064 5.588,4.064 6.858,4.064 7.112,4.318 7.112,5.08 6.858,5.08 6.35,5.588 6.35,6.096 6.35,6.604 5.334,7.62
GND on Top Layer "GND" (solid, remove dead copper, pour order 10): 0.762,13.462 0.254,12.954 0.254,12.446 0.254,7.112 0.254,0.508 0.762,0 1.524,0 19.558,0 20.066,0.508 20.066,0.762 20.066,4.572 18.034,6.604 17.018,7.62 17.018,9.906 17.018,14.732 16.002,15.748 15.494,15.748 10.414,15.748 8.89,14.224 1.524,14.224

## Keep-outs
Keep-Out Layer:
  text ".Layer_Name" at 14.656,-21.806 h1.52

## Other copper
Top Layer:
  text ".Layer_Name" at 14.656,-21.806 h1.52
Bottom Layer:
  text ".Layer_Name" at 14.656,-21.806 h1.52

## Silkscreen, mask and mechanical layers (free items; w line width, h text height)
Top Overlay:
  lines w0.254: 34.544,3.302 34.798,3.556 39.878,3.556
  text "PMP21455" at 0.508,16.002 h1.52
  text ".Layer_Name" at 14.656,-21.806 h1.52
Bottom Overlay:
  text ".Layer_Name" at 14.656,-21.806 h1.52
Top Paste:
  text ".Layer_Name" at 14.656,-21.806 h1.52
Bottom Paste:
  text ".Layer_Name" at 14.656,-21.806 h1.52
Top Solder:
  text ".Layer_Name" at 14.656,-21.806 h1.52
  text ".Layer_Name" at 14.656,-21.806 h1.52
Bottom Solder:
  text ".Layer_Name" at 14.656,-21.806 h1.52
Drill Guide:
  text ".Layer_Name" at 14.656,-21.806 h1.52
M1 Board Outline:
  the board outline again, w0.178
  text ".Layer_Name" at 14.656,-21.806 h1.52
M2 Board Dimensions:
  rectangle: 3.175,-10.16 12.7,-6.985
  rectangle: 0,-6.985 3.175,-3.81
  lines w0.178: 0,-6.985 25.4,-6.985 ; 3.175,-10.16 3.175,-3.81 ; 6.35,-10.16 6.35,-3.81 ; 12.7,-10.16 12.7,-3.81 ; 19.05,-10.16 19.05,-3.81 ; 0,-10.16 0,-3.81 25.4,-3.81 25.4,-10.16 0,-10.16
  text ".Layer_Name" at 14.656,-21.806 h1.52
M3 3D STEP Top:
  text ".Layer_Name" at 14.656,-21.806 h1.52
M4 3D STEP Bottom:
  text ".Layer_Name" at 14.656,-21.806 h1.52
M5 Assembly Top:
  lines w0.254: -7.417,-23.626 160.223,-23.626 ; -7.417,-18.462 160.274,-18.462 ; -7.417,-13.297 -7.417,-28.791 94.31,-28.791 160.274,-28.791 160.274,-13.297 -7.404,-13.297 -7.404,-28.791 32.614,-28.791 ; 55.194,-28.791 55.194,-13.297 ; 87.376,-18.462 87.376,-13.297 ; 108.712,-18.462 108.712,-13.297 ; 124.511,-28.956 124.511,-23.804
  text "COMPONENTS MARKED 'DNP' SHOULD NOT BE POPULATED." at 29.299,-8.09 h1.52
  text "ASSEMBLY VARIANT:" at 29.286,-11.024 h1.52
  text ".VariantName" at 55.601,-11.024 h1.52
  text "PCB VIEWED FROM TOP SIDE" at -5.804,-16.654 h1.52
  text "BOARD #:" at 57.099,-16.654 h1.52
  text ".PRJ_Number" at 70.955,-16.654 h1.52
  text "REV:" at 92.405,-16.654 h1.52
  text ".PCB_Rev" at 99.809,-16.654 h1.52
  text "SVN REV:" at 113.69,-16.654 h1.52
  text ".VersionControl_RevNumber" at 126.543,-16.654 h1.52
  text "TID #:" at 57.099,-21.819 h1.52
  text ".TID" at 70.955,-21.819 h1.52
  text "PLOT NAME =" at -5.804,-27.034 h1.52
  text ".plot_File_Name" at 14.656,-27.034 h1.52
  text "GENERATED    :" at 57.15,-27.034 h1.52
  text ".Print_Date" at 79.235,-27.034 h1.52
  text ".Print_Time" at 97.752,-27.034 h1.52
  text "TEXAS INSTRUMENTS" at 129.87,-27.034 h1.52
M6 Assembly Bottom:
  lines w0.254: -7.429,-18.474 160.261,-18.474 ; -7.379,-23.639 160.261,-23.639 ; 28.334,-28.969 28.334,-23.817 ; 44.133,-18.474 44.133,-13.31 ; 65.468,-18.474 65.468,-13.31 ; 97.65,-28.804 97.65,-13.31 ; 120.231,-28.804 160.249,-28.804 160.249,-13.31 -7.429,-13.31 -7.429,-28.804 58.534,-28.804 160.261,-28.804 160.261,-13.31
  text "COMPONENTS MARKED 'DNP' SHOULD NOT BE POPULATED." at 154.991,-8.077 h1.52
  text ".VariantName" at 128.473,-11.024 h1.52
  text "ASSEMBLY VARIANT:" at 154.864,-11.024 h1.52
  text ".VersionControl_RevNumber" at 26.302,-16.667 h1.52
  text "SVN REV:" at 39.154,-16.667 h1.52
  text ".PCB_Rev" at 53.035,-16.667 h1.52
  text "REV:" at 60.439,-16.667 h1.52
  text ".PRJ_Number" at 81.89,-16.667 h1.52
  text "BOARD #:" at 95.745,-16.667 h1.52
  text "PCB VIEWED FROM BOTTOM SIDE" at 158.648,-16.667 h1.52
  text ".TID" at 81.89,-21.831 h1.52
  text "TID #:" at 95.745,-21.831 h1.52
  text "TEXAS INSTRUMENTS" at 22.974,-27.047 h1.52
  text ".Print_Time" at 55.093,-27.047 h1.52
  text ".Print_Date" at 73.609,-27.047 h1.52
  text "GENERATED    :" at 95.694,-27.047 h1.52
  text ".plot_File_Name" at 138.189,-27.047 h1.52
  text "PLOT NAME =" at 158.648,-27.047 h1.52
M9 Title Sheet:
  drawing of 57 lines, arcs and shapes, not listed
  text "1" at 18.792,204.127 h1.78
  text "2" at 82.182,204.127 h1.78
  text "3" at 145.411,204.127 h1.78
  text "4" at 209.08,204.127 h1.78
  text "5" at 272.555,204.127 h1.78
  text "6" at 336.182,204.127 h1.78
  text "A" at -10.579,175.095 h1.78
  text "A" at 365.341,175.095 h1.78
  text "B" at -10.579,114.643 h1.78
  text "B" at 365.341,114.643 h1.78
  text "C" at -10.579,54.318 h1.78
  text "C" at 365.341,54.318 h1.78
  text "PROJECT TITLE:" at 288.125,7.048 h1.14
  text ".PRJ_Title" at 289.395,3.662 h1.78
  text "DESIGNED FOR:" at 288.125,-0.597 h1.14
  text ".PRJ_Customer" at 289.395,-4.153 h1.78
  text "D" at -10.579,-5.88 h1.78
  text "D" at 365.341,-5.88 h1.78
  text "FILE NAME:" at 288.125,-8.217 h1.14
  text ".PCB_File_Name_No_Path" at 289.395,-11.265 h1.78
  text "Texas Instruments (TI) and/or its licensors do not warrant the accuracy or completeness of this specification" at 161.9,-15.376 h1.14
  text "ENGINEER:" at 288.125,-15.583 h1.14
  text "LAYOUT BY:" at 326.352,-15.583 h1.14
  text "or any information contained therein. TI and/or its licensors do not warrant that this design will meet" at 160.757,-18.237 h1.14
  text ".PRJ_Engineer" at 289.395,-19.52 h1.78
  text ".PCB_Layout" at 327.635,-19.52 h1.78
  text "the specifications, will be suitable for your application or fit for any particular purpose, or will operate in" at 160.757,-21.099 h1.14
  text ".Layer_Name" at 14.656,-21.806 h1.52
  text "ALTIUM DESIGNER VERSION:" at 326.352,-23.457 h1.14
  text "an implementation. TI and/or its licensors do not warrant that the design is production worthy. You should" at 160.757,-23.961 h1.14
  text "completely validate and test your design implementation to confirm the system functionality for your application." at 161.9,-26.822 h1.14
  text ".print_Scale" at 289.395,-26.843 h1.78
  text ".Application_BuildNumber" at 327.635,-26.843 h1.78
  text "1" at 18.792,-32.093 h1.78
  text "2" at 82.182,-32.093 h1.78
  text "3" at 145.411,-32.093 h1.78
  text "4" at 209.08,-32.093 h1.78
  text "5" at 272.555,-32.093 h1.78
  text "6" at 336.182,-32.093 h1.78
M10 Fab Notes:
  drawing of 173 lines, arcs and shapes, not listed
  text "DESIGN INFORMATION" at 314.402,157.505 h1.52
  text "MIN. TRACK WIDTH:" at 298.03,152.933 h1.52
  text "8" at 325.874,152.933 h1.52
  text "MIL" at 329.805,152.933 h1.52
  text "MIN. CLEARANCE:" at 298.03,149.581 h1.52
  text "0.2" at 324.35,149.581 h1.52
  text "mm" at 329.805,149.581 h1.52
  text "MIN. VIA PAD SIZE:" at 298.03,146.228 h1.52
  text "24" at 325.113,146.228 h1.52
  text "MIL" at 329.805,146.228 h1.52
  text "0.05mm (2MIL)" at 315.683,142.628 h1.52
  text "MINIMUM ANNULAR RING" at 289.667,142.52 h1.52
  text "EXTERNAL" at 333.666,142.52 h1.52
  text "PER" at 294.747,139.522 h1.52
  text "IPC-D-275 CLASS 2 LEVEL C" at 300.335,139.522 h1.52
  text "MIL, HOLES" at 338.136,136.67 h1.52
  text "+/-" at 328.168,136.652 h1.52
  text "+/-" at 349.86,136.652 h1.52
  text "REGISTRATION TOLERANCES:" at 289.667,136.525 h1.52
  text "METAL" at 320.142,136.525 h1.52
  text "5" at 334.777,136.525 h1.52
  text "3" at 355.935,136.525 h1.52
  text "MIL" at 358.888,136.525 h1.52
  text "+/-" at 349.86,133.655 h1.52
  text "HOLE SIZE TOLERANCE (UNLESS OTHERWISE SPECIFIED):" at 289.667,133.528 h1.52
  text "3" at 355.935,133.528 h1.52
  text "MIL" at 358.888,133.528 h1.52
  text "MATERIAL:" at 287.768,128.208 h1.52
  text "FR-4 High Tg" at 312.824,124.643 h1.52
  text "FR-408" at 298.462,124.425 h1.52
  text "OTHER" at 336.257,124.425 h1.52
  text "X" at 308.889,124.333 h1.52
  text "62 MIL (1.6mm) +/-10%" at 306.592,120.292 h1.52
  text "THICKNESS:" at 289.667,120.184 h1.52
  text "X" at 303.337,120.184 h1.52
  text "OTHER" at 339.229,120.184 h1.52
  text "TOLERANCE:" at 289.667,116.17 h1.52
  text "X" at 310.986,116.17 h1.52
  text "ANSI IPC-6012 TYPE 3 CLASS 2" at 315.734,116.17 h1.52
  text "OTHER +/-" at 315.734,112.208 h1.52
  text "BOW & TWIST:" at 289.667,108.22 h1.52
  text "X" at 310.986,108.22 h1.52
  text "ANSI IPC-6012 TYPE 3 CLASS 2" at 315.734,108.22 h1.52
  text "OTHER +/-" at 315.734,104.194 h1.52
  text "DRILLING:" at 287.768,100.676 h1.52
  text "REFERENCE:" at 289.667,97.705 h1.52
  text "X" at 306.132,97.705 h1.52
  text "AS SHOWN" at 310.882,97.705 h1.52
  text "X" at 329.018,97.705 h1.52
  text "NC_DRILL FILES" at 332.498,97.705 h1.52
  text "PTH COPPER THICKNESS:" at 289.667,93.691 h1.52
  text "X" at 318.375,93.691 h1.52
  text "20-30 um" at 321.855,93.691 h1.52
  text "OTHER" at 340.067,93.691 h1.52
  text "BOARD FINISH:" at 287.768,89.653 h1.52
  text "SILKSCREEN:" at 291.711,86.656 h1.52
  text "X" at 315.81,86.656 h1.52
  text "TOP" at 319.01,86.656 h1.52
  text "X" at 328.764,86.656 h1.52
  text "BOTTOM" at 331.99,86.656 h1.52
  text "SILKSCREEN COLOR:" at 291.711,82.414 h1.52
  text "X" at 315.783,82.414 h1.52
  text "WHITE" at 319.01,82.414 h1.52
  text "OTHER" at 331.99,82.414 h1.52
  text "X" at 319.111,78.37 h1.52
  text "GREEN" at 322.338,78.37 h1.52
  text "OTHER" at 338.035,78.37 h1.52
  text "SOLDER RESIST COLOR:" at 291.711,78.096 h1.52
  text "X" at 319.111,74.052 h1.52
  text "MATTE" at 322.338,74.052 h1.52
  text "SEMI-GLOSS" at 338.023,74.036 h1.52
  text "IMMERSION GOLD (ENIG)" at 314.718,69.264 h1.52
  text "ENEPIG" at 348.691,69.18 h1.52
  text "SURFACE FINISH:" at 287.768,69.155 h1.52
  text "X" at 309.969,69.155 h1.52
  text "IMM. TIN/SILVER OR EQUIV" at 296.139,65.167 h1.52
  text "OTHER" at 332.498,65.167 h1.52
  text "ARRAY/PANEL:" at 287.768,60.621 h1.52
  text "CUT AND TRIM PER M1 BOARD OUTLINE" at 314.718,60.512 h1.52
  text "N.C. ROUTE" at 314.718,56.658 h1.52
  text "X" at 331.964,56.658 h1.52
  text "V. SCORE" at 336.714,56.658 h1.52
  text "CERTIFICATION:" at 287.768,53.178 h1.52
  text "MATERIALS AND WORKMANSHIP FOR ALL PCBS" at 306.183,53.178 h1.52
  text "TO MEET OR EXCEED THE REQUIREMENTS OF:" at 306.183,50.689 h1.52
  text "X" at 296.696,47.222 h1.52
  text "ANSI IPC-A-600F CLASS ->" at 300.227,47.222 h1.52
  text "X" at 341.859,47.222 h1.52
  text "2" at 344.88,47.222 h1.52
  text "1" at 336.879,47.184 h1.52
  text "3" at 353.872,47.184 h1.52
  text "X" at 317.373,43.171 h1.52
  text "RoHS" at 320.852,43.171 h1.52
  text "OTHER" at 337.22,43.171 h1.52
  text "PER ORDER" at 347.305,43.171 h1.52
  text "ALL BOARDS MUST MEET OR EXCEED UL94-V0 REQUIREMENTS." at 288.468,38.964 h1.52
  text "PCB MUST BEAR THE UL94V-0 UL REGISTERED MATERIAL ID NUMBER" at 288.468,35.916 h1.52
  text "ADDITIONAL REQUIREMENTS:" at 287.768,31.512 h1.52
  text "MICROSECTION:" at 289.667,28.591 h1.52
  text "YES" at 312.673,28.591 h1.52
  text "REQUIRED" at 334.555,24.625 h1.52
  text "BARE BOARD ELEC. TEST:" at 289.667,24.553 h1.52
  text "NONE" at 322.833,24.553 h1.52
  text "X" at 331.329,24.553 h1.52
  text "PER ORDER" at 349.592,24.553 h1.52
  text ".Layer_Name" at 14.656,-21.806 h1.52
M11 Gerber Information:
  lines w0.254: -7.417,-23.626 160.223,-23.626 ; -7.417,-18.462 160.274,-18.462 ; -7.417,-13.297 -7.417,-28.791 94.31,-28.791 160.274,-28.791 160.274,-13.297 -7.404,-13.297 -7.404,-28.791 32.614,-28.791 ; 55.194,-28.791 55.194,-13.297 ; 87.376,-18.462 87.376,-13.297 ; 108.712,-18.462 108.712,-13.297 ; 124.511,-28.956 124.511,-23.804
  text "ALL ARTWORK VIEWED FROM TOP SIDE" at -5.804,-16.654 h1.52
  text "BOARD #:" at 57.099,-16.654 h1.52
  text ".PRJ_Number" at 70.955,-16.654 h1.52
  text "REV:" at 92.405,-16.654 h1.52
  text ".PCB_Rev" at 99.809,-16.654 h1.52
  text "SVN REV:" at 113.69,-16.654 h1.52
  text ".VersionControl_RevNumber" at 126.543,-16.654 h1.52
  text "LAYER NAME =" at -5.804,-21.806 h1.52
  text "TID #:" at 57.099,-21.819 h1.52
  text ".TID" at 70.955,-21.819 h1.52
  text "PLOT NAME =" at -5.804,-27.034 h1.52
  text ".plot_File_Name" at 14.656,-27.034 h1.52
  text "GENERATED    :" at 57.15,-27.034 h1.52
  text ".Print_Date" at 79.235,-27.034 h1.52
  text ".Print_Time" at 97.752,-27.034 h1.52
  text "TEXAS INSTRUMENTS" at 129.87,-27.034 h1.52
M12 Stackup:
  drawing of 191 lines, arcs and shapes, not listed
  text "Layer" at 248.675,198.882 h1.52
  text "Name" at 259.086,198.882 h1.52
  text "Material" at 282.702,198.882 h1.52
  text "Thickness" at 304.54,198.882 h1.52
  text "Constant" at 321.046,198.882 h1.52
  text "Board Layer Stack" at 335.52,198.882 h1.52
  text "1" at 248.675,195.834 h1.52
  text "Top Overlay" at 259.086,195.834 h1.52
  text "2" at 248.675,192.786 h1.52
  text "Top Solder" at 259.086,192.786 h1.52
  text "Solder Resist" at 282.702,192.786 h1.52
  text "0.40mil" at 304.54,192.786 h1.52
  text "3.5" at 321.046,192.786 h1.52
  text "3" at 248.675,189.738 h1.52
  text "Top Layer" at 259.086,189.738 h1.52
  text "Copper" at 282.702,189.738 h1.52
  text "1.40mil" at 304.54,189.738 h1.52
  text "4" at 248.675,186.69 h1.52
  text "Dielectric1" at 259.086,186.69 h1.52
  text "FR-4" at 282.702,186.69 h1.52
  text "59.20mil" at 304.54,186.69 h1.52
  text "4.8" at 321.046,186.69 h1.52
  text "5" at 248.675,183.642 h1.52
  text "Bottom Layer" at 259.086,183.642 h1.52
  text "Copper" at 282.702,183.642 h1.52
  text "1.40mil" at 304.54,183.642 h1.52
  text "6" at 248.675,180.594 h1.52
  text "Bottom Solder" at 259.086,180.594 h1.52
  text "Solder Resist" at 282.702,180.594 h1.52
  text "0.40mil" at 304.54,180.594 h1.52
  text "3.5" at 321.046,180.594 h1.52
  text "7" at 248.675,177.546 h1.52
  text "Bottom Overlay" at 259.086,177.546 h1.52
  text ".Layer_Name" at 14.656,-21.806 h1.52
M13 Component Bodies Top:
  text ".Layer_Name" at 14.656,-21.806 h1.52
M14 Component Bodies Bottom:
  text ".Layer_Name" at 14.656,-21.806 h1.52
M15 Courtyards Top:
  text ".Layer_Name" at 14.656,-21.806 h1.52
M16 Courtyards Bottom:
  text ".Layer_Name" at 14.656,-21.806 h1.52
Drill Drawing:
  text ".Layer_Name" at 14.656,-21.806 h1.52
M17 Embedded Cavity:
  text ".Layer_Name" at 14.656,-21.806 h1.52
M18 Embedded Assembly:
  text ".Layer_Name" at 14.656,-21.806 h1.52
M19 Embedded Keepout:
  text ".Layer_Name" at 14.656,-21.806 h1.52

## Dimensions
0,0 to 41,0 on M2 Board Dimensions
0,0 to 0,30 on M2 Board Dimensions
0,-10.16 to 25.4,-10.16 on M2 Board Dimensions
